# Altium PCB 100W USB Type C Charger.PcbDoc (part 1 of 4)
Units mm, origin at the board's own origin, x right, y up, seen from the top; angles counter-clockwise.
Board outline 79.45 x 55.68 mm, 4 copper layers (Top Layer, Signal Layer 1, Signal Layer 2, Bottom Layer), stack 1.565 mm thick; 161 components, 84 nets, 462 pads, 2175 vias.
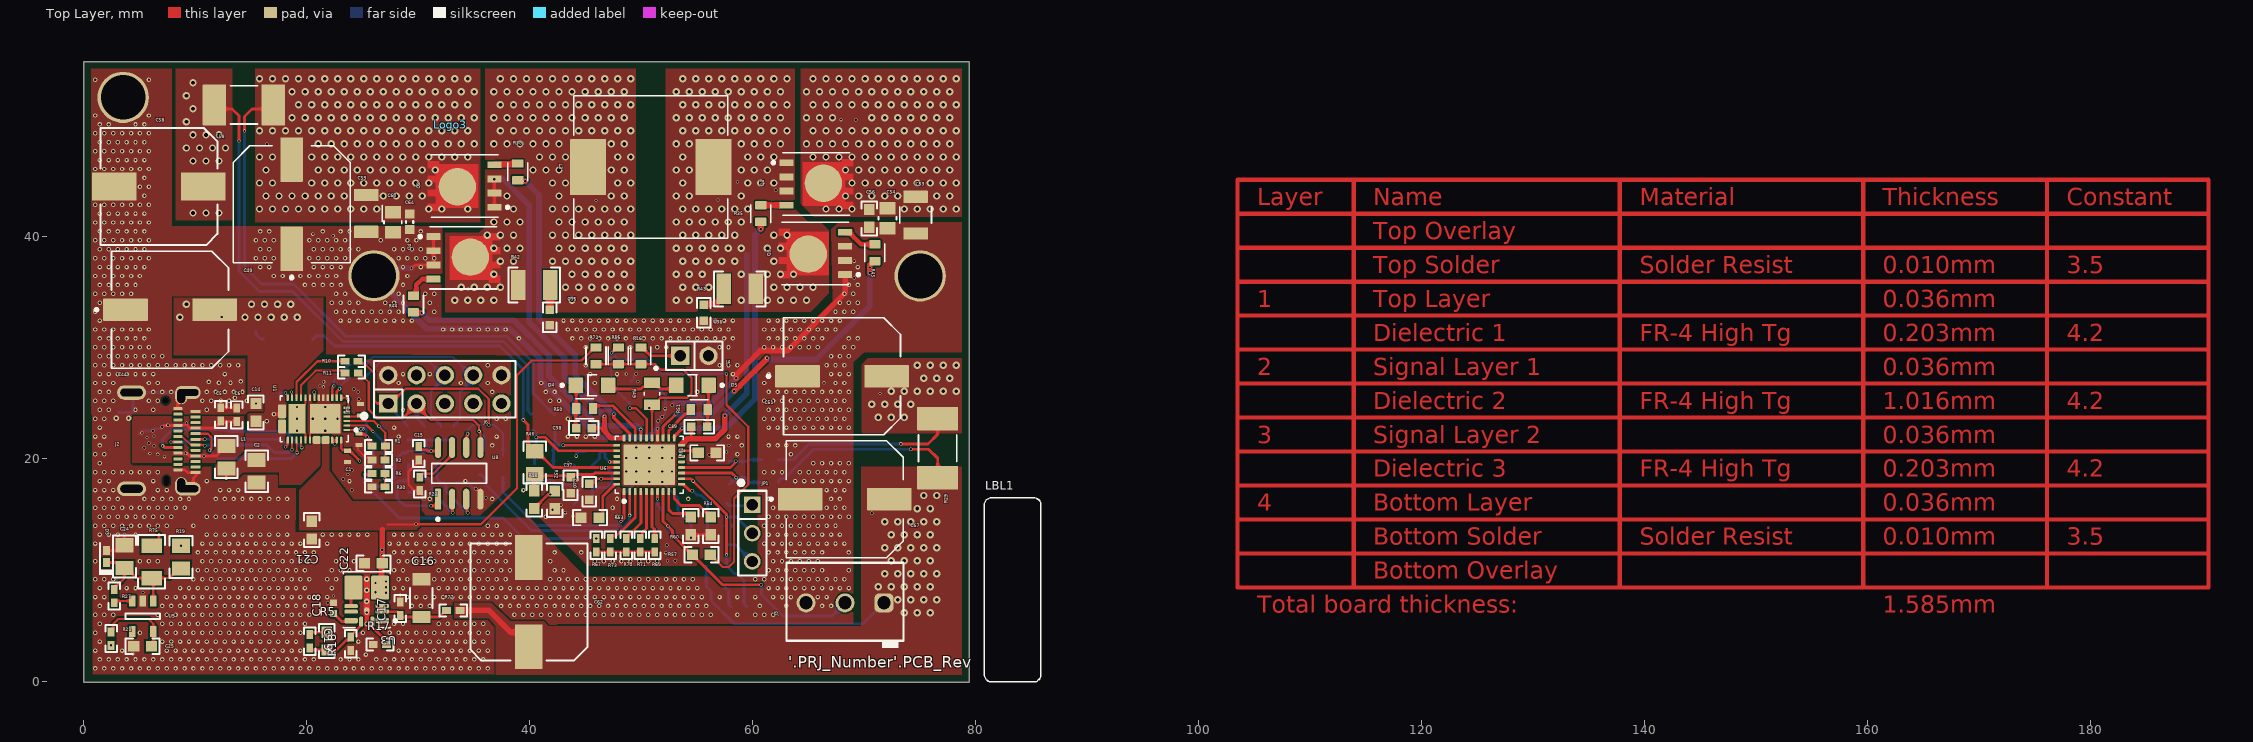
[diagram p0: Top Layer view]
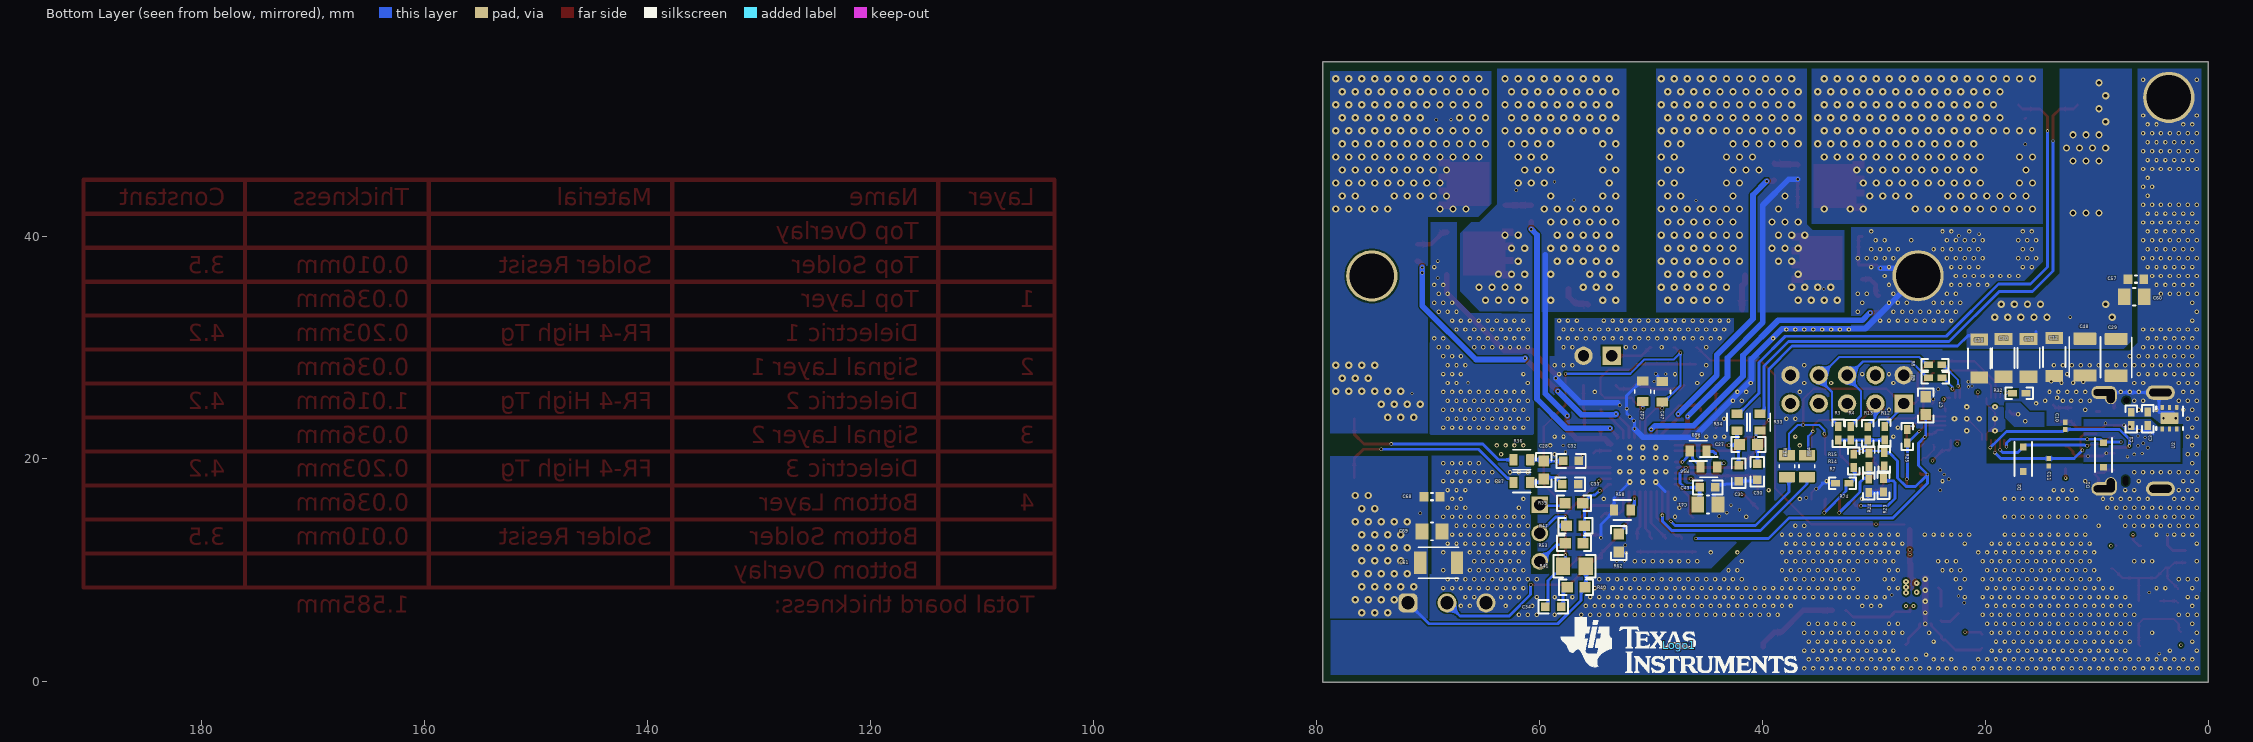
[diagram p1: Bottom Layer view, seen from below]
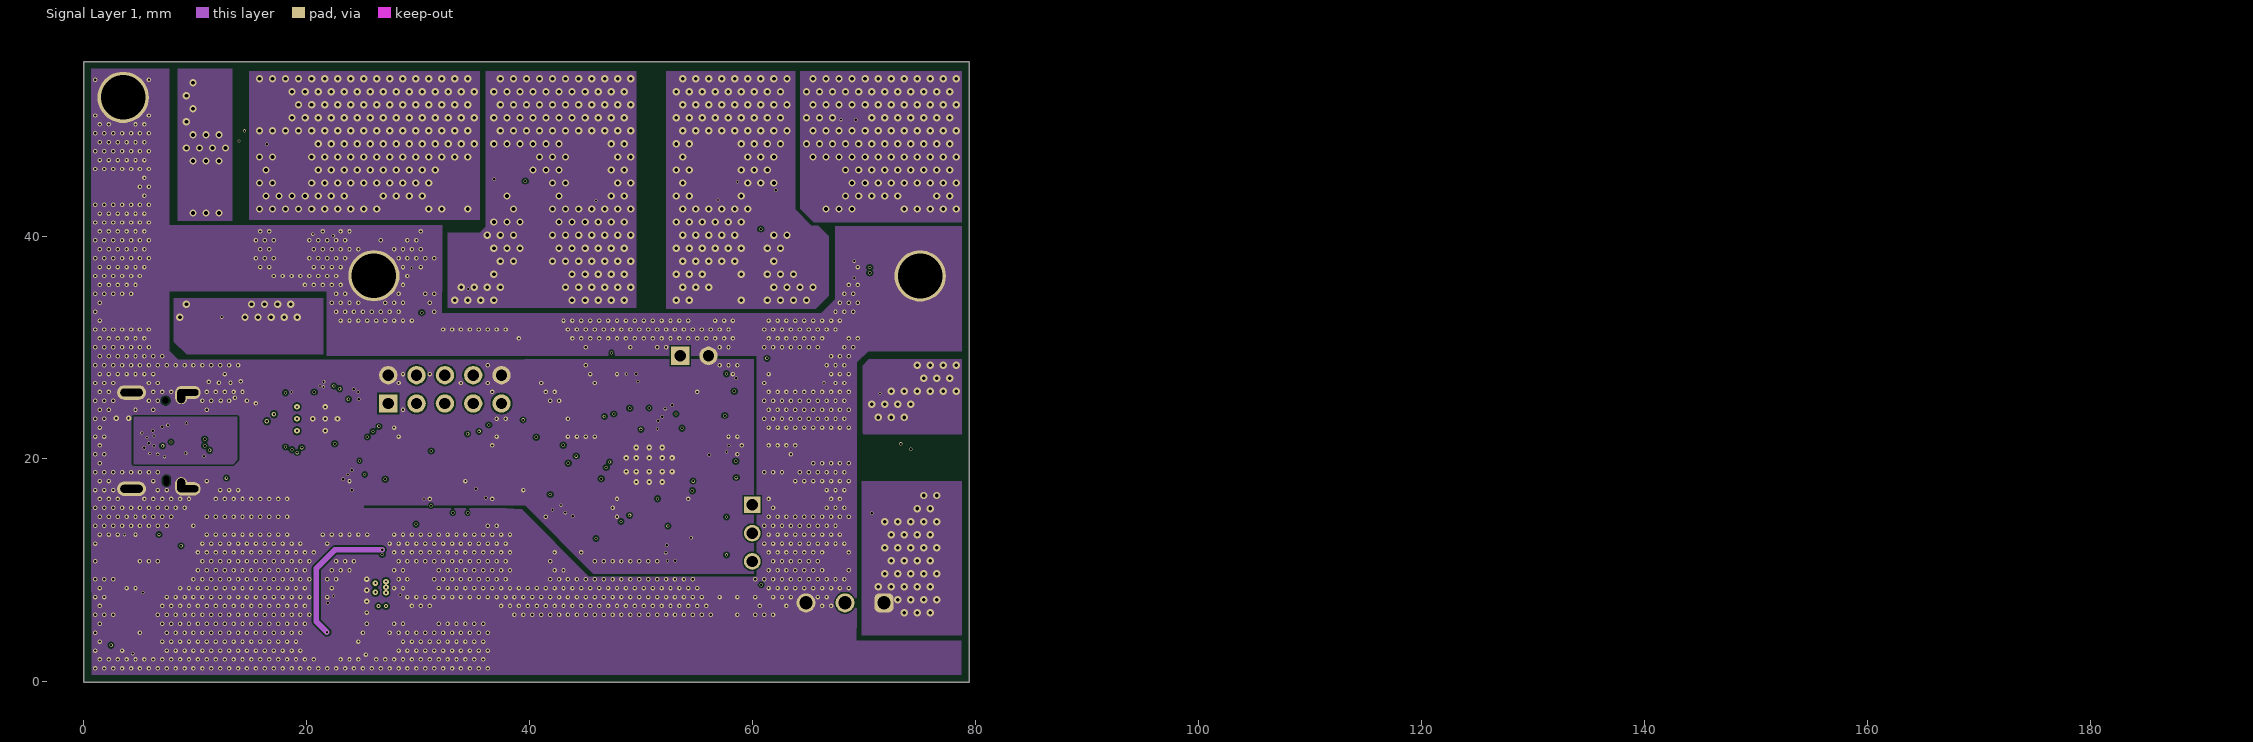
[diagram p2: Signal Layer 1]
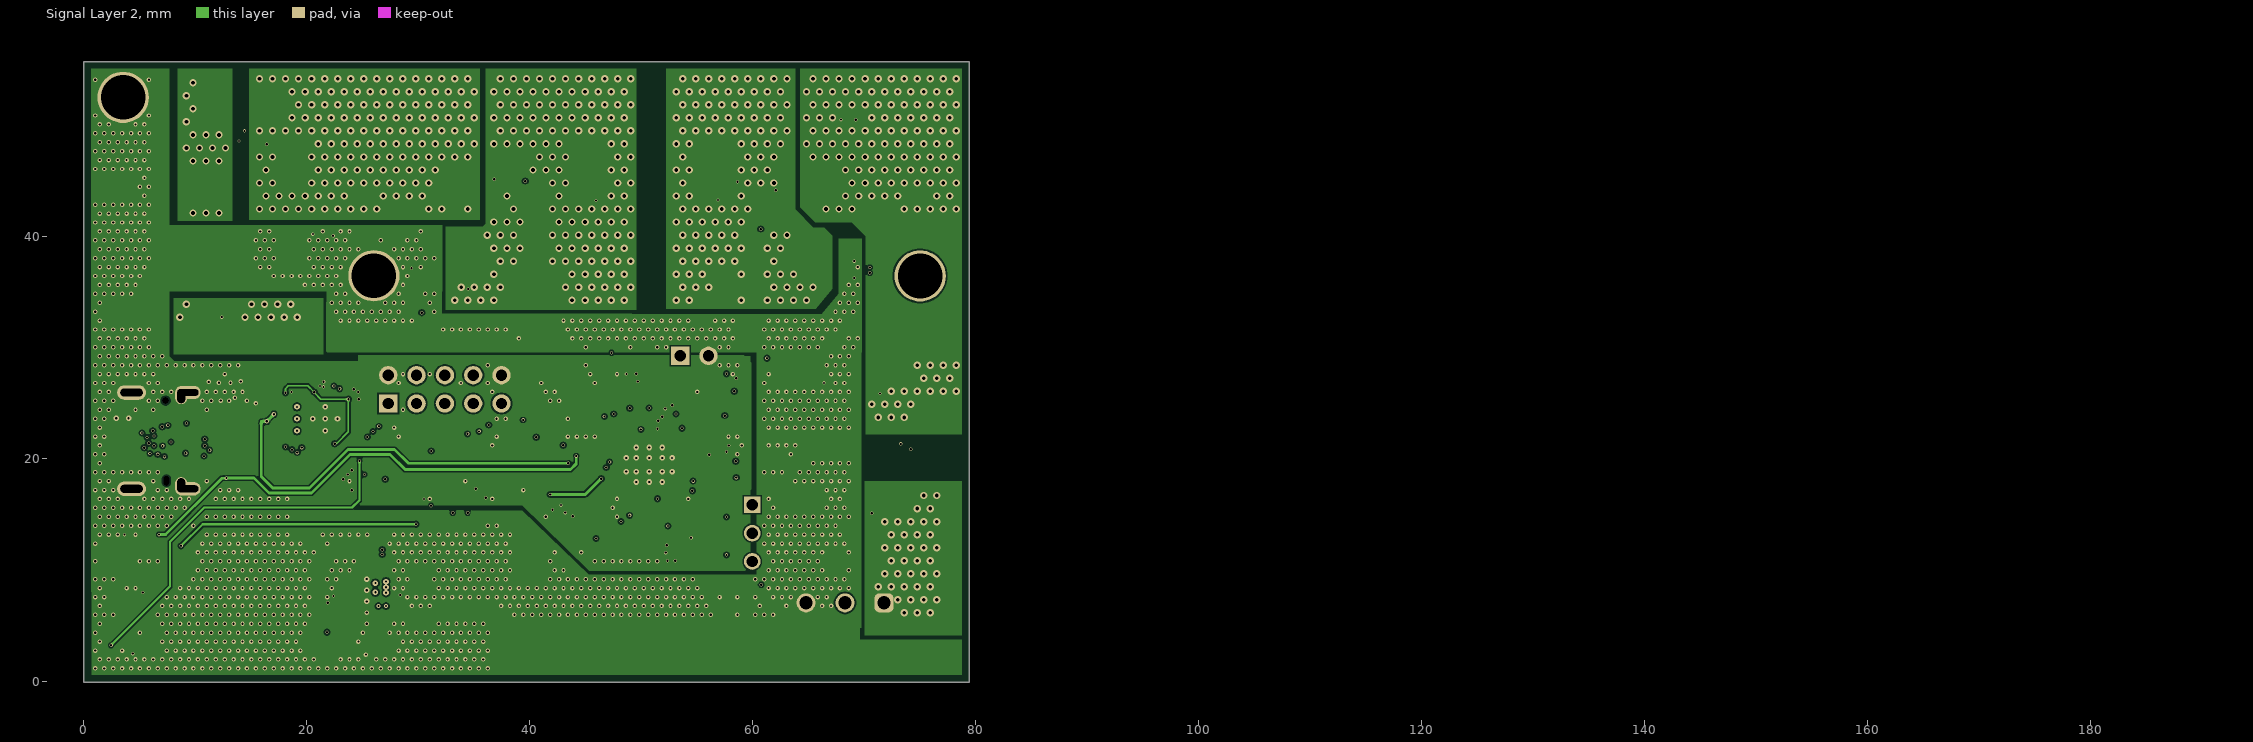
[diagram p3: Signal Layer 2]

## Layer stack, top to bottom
Top Solder: solder mask 0.0102, Solder Resist, Dk 3.5
Top Layer: signal copper 0.0356
Dielectric 1: prepreg 0.2032, FR-4 High Tg, Dk 4.2
Signal Layer 1: signal copper 0.0356
Dielectric 2: core 1.016, FR-4 High Tg, Dk 4.2
Signal Layer 2: signal copper 0.0356
Dielectric 3: prepreg 0.2032, FR-4 High Tg, Dk 4.2
Bottom Layer: signal copper 0.0356
Bottom Solder: solder mask 0.0102, Solder Resist, Dk 3.5

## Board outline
-0.018,-0.02 -0.018,55.656 79.433,55.656 79.433,-0.02

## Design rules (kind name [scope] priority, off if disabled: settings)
AcuteAngle [All] p1: minimum=4.50000000000000E+0001 checktracksonly=FALSE
AssemblyTestPointUsage [All] p1: valid=2
BoardOutlineClearance BoardOutlineClearance_MountingHoles [OnCopper and InComponentClass('Mounting Holes')] p1: gap=1 ignorepadtopadclearanceinfootprint=FALSE
BoardOutlineClearance BoardOutlineClearance_Poly [OnCopper and IsPoly] p2: gap=0.635 ignorepadtopadclearanceinfootprint=FALSE
BoardOutlineClearance [OnCopper and Not InComponentClass('Logo') and not InComponentClass('FiducialMark') and not InRegion(1000,500,4000,800) and not InPoly] p3: gap=1.016 ignorepadtopadclearanceinfootprint=FALSE
Clearance "VBUS V50" [(InComponent('U1') AND InNet('VBUS')) Or InComponent('U1') And InNet('P5V0')] p1: gap=0.15 ignorepadtopadclearanceinfootprint=TRUE
Clearance Clearance_Poly [InPolygon] p2: gap=0.15 ignorepadtopadclearanceinfootprint=TRUE
Clearance [All] p3: gap=0.15 ignorepadtopadclearanceinfootprint=TRUE
ComponentClearance ComponentClearance_MountingHoles_FiducialMarks [InComponentClass('Mounting Holes') vs InComponentClass('FiducialMark')] p1: gap=1.27 collisioncheckmode=3 verticalgap=0.254 showdistances=FALSE
ComponentClearance ComponentClearance_Shunt [InComponentClass('Header') vs InComponentClass('Shunt')] p2: gap=0.15 collisioncheckmode=3 verticalgap=0.15 showdistances=FALSE
ComponentClearance ComponentClearance_Logo [InComponentClass('Logo')] p3: gap=0.254 collisioncheckmode=3 verticalgap=0.254 showdistances=FALSE
ComponentClearance ComponentClearance_ScrewToNut [(HasFootprint('NY PMS 440 0025 PH')) vs (HasFootprint('Keystone_1902C'))] p4: gap=0.127 collisioncheckmode=3 verticalgap=0.254 showdistances=FALSE
ComponentClearance ComponentClearance_MountingHoles [InComponentClass('Mounting Holes')] p5: gap=0.254 collisioncheckmode=3 verticalgap=2540 showdistances=FALSE
ComponentClearance ComponentClearance_SmallPassives [HasFootprint('0201*') or HasFootprint('0402*') or HasFootprint('0508') or HasFootprint('0603*') or HasFootprint('0612') or HasFootprint('0805*') or HasFootprint('0815*') or HasFootprint('0830*') or HasFootprint('1206*') or HasFootprint('1210*') or HasFootprint('1808*') or HasFootprint('1812*') or HasFootprint('1825*') or HasFootprint('2010*') or HasFootprint('2220*') or HasFootprint('2225*') or HasFootprint('2512*') or HasFootprint('2728*') or HasFootprint('3518*') vs HasFootprint('0201*') or HasFootprint('0402*') or HasFootprint('0508') or HasFootprint('0603*') or HasFootprint('0612') or HasFootprint('0805*') or HasFootprint('0815*') or HasFootprint('0830*') or HasFootprint('1206*') or HasFootprint('1210*') or HasFootprint('1808*') or HasFootprint('1812*') or HasFootprint('1825*') or HasFootprint('2010*') or HasFootprint('2220*') or HasFootprint('2225*') or HasFootprint('2512*') or HasFootprint('2728*') or HasFootprint('3518*')] p6: gap=0.254 collisioncheckmode=3 verticalgap=0.254 showdistances=FALSE
ComponentClearance ComponentClearance_THtoSMT [IsThruComponent vs IsSMTComponent] p7: gap=0.254 collisioncheckmode=3 verticalgap=0.254 showdistances=FALSE
ComponentClearance ComponentClearance_THtoTH [IsThruComponent vs IsThruComponent] p8: gap=0.1 collisioncheckmode=3 verticalgap=0.1 showdistances=FALSE
ComponentClearance [All] p9: gap=0.254 collisioncheckmode=3 verticalgap=0.254 showdistances=FALSE
DiffPairsRouting [All] p1: maxlimit=2.54 minlimit=0.254 mostfreqgap=0.254 toplayer_minwidth=0.381 toplayer_maxwidth=0.381 toplayer_prefwidth=0.381 midlayer1_minwidth=0.381 midlayer1_maxwidth=0.381 midlayer1_prefwidth=0.381 midlayer2_minwidth=0.381 midlayer2_maxwidth=0.381 midlayer2_prefwidth=0.381 bottomlayer_minwidth=0.381 bottomlayer_maxwidth=0.381 bottomlayer_prefwidth=0.381 maxuncoupledlength=25.4
FabricationTestPointUsage TestPointUsage [All] p1: valid=2 allowmultiple=FALSE
FabricationTestpoint Testpoint [All] p1: side=3 testpointundercomponent=TRUE minsize=1.016 maxsize=2.54 preferedsize=1.524 minholesize=0 maxholesize=1.016 preferedholesize=0.813 testpointgrid=0.025 allowsidetop=TRUE allowsidebottom=TRUE usegrid=TRUE gridtolerance=0
FanoutControl Fanout_LCC [IsLCC] p1: bgadir=Out bgaviamode=Centered fanoutstyle=Auto fanoutdirection=Alternating viagrid=0.025 // Fanout_LCC (Default Rule)
FanoutControl Fanout_BGA [IsBGA] p2: bgadir=Out bgaviamode=Centered fanoutstyle=Auto fanoutdirection=Alternating viagrid=0.025 // Fanout_BGA (Default Rule)
FanoutControl Fanout_Default [All] p4: bgadir=Out bgaviamode=Centered fanoutstyle=Auto fanoutdirection=Alternating viagrid=0.025 // Fanout_Default (Default Rule)
FanoutControl Fanout_Small [(CompPinCount < 5)] p5: bgadir=Out bgaviamode=Centered fanoutstyle=Auto fanoutdirection=OutThenIn viagrid=0.025 // Fanout_Small (Default Rule)
HoleSize [All] p1: absolutevalues=TRUE maxlimit=6.375 minlimit=0.2 maxpercent=80.000 minpercent=20.000
MinimumAnnularRing MinimumAnnularRing_ThermalPadVias [IsVia and InAnyComponent] p1: minimumring=0.15
MinimumAnnularRing [All] p2: minimumring=0.2
MinimumSolderMaskSliver MinimumSolderMaskSliver_Logo [InComponentClass('Logo') vs InComponentClass('Logo')] p1: minsoldermaskwidth=0.018
MinimumSolderMaskSliver [All] p2: minsoldermaskwidth=0.1
PlaneConnect [All] p1: planeconnectstyle=Relief reliefexpansion=0.254 reliefentries=4 reliefconductorwidth=0.254 reliefairgap=0.254
PolygonConnect [All] p1: connectstyle=Direct reliefconductorwidth=0.254 reliefentries=4 polygonreliefangle="90 Angle" airgapwidth=0.254
RoutingVias ThermalPadVias [IsVia and InAnyComponent] p1: holewidth=0.2 width=0.5 viastyle="Through Hole" minholewidth=0.2 minwidth=0.5 maxholewidth=0.33 maxwidth=0.6
RoutingVias [All] p2: holewidth=0.406 width=0.864 viastyle="Through Hole" minholewidth=0.2 minwidth=0.61 maxholewidth=1.016 maxwidth=1.651
SilkToBoardRegionClearance [Not ((IsComment or IsDesignator) And (Hide <> 'False')) and not InRegion(1000,500,4000,800)] p1:
SilkToSilkClearance SilkToSilkClearance_Pb-FreeLogo [(HasFootprint('Pb-Free_Overlay_Medium') OR HasFootprint('Pb-Free_Overlay_Small')) vs (HasFootprint('Pb-Free_Overlay_Medium') OR HasFootprint('Pb-Free_Overlay_Small'))] p1: silktosilkclearance=0
SilkToSilkClearance [All] p2: silktosilkclearance=0.1
SilkToSolderMaskClearance SilkToComponentPadClearance [(IsPad or IsFill or IsRegion) and InAnycomponent] p1: minsilkscreentomaskgap=0.127 clearancetoexposedcopper=TRUE
SilkToSolderMaskClearance "Silk to Solder Mask Opening" [All] p2: minsilkscreentomaskgap=0.1 clearancetoexposedcopper=FALSE
SolderMaskExpansion [All] p1: expansion=0.05 istentingtop=FALSE
UnRoutedNet [All] p1: checkbadconnections=TRUE
Width [All] p1: maxlimit=2.54 minlimit=0.152 preferedwidth=0.254
14 further rules are at their usual default settings.

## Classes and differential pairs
net class HHV: BAT HIDRV2 NetC36_1 NetC39_1 NetQ1_4 P_OUT SRN SRP SW2
net class LV: LDO_3V3 LODRV1 LODRV2 PGND
net class HV: ACN ACP ACUV HIDRV1 NetC35_1 NetC38_2 NetQ2_4 PPHV SW1 VSYS
component class "PD Controller": C1 C2 C3 C4 C5 C6 C7 C8 C9 C10 C11 C12 C13 C14 C15 C16 C17 C18 C19 C20 C21 C22 C24 C25 C70 D1 D2 D3 J2 J6 L1 R1 R2 R3 R4 R5 R6 R7 R8 R9 R10 R11 R12 R13 R14 R15 R17 R18 R19 R21 R22 R23 R24 R25 R27 R30 R32 R74 R75 R77 U1 U2 U3 U5 U8
component class Header: J4 J6 JP1
component class "Charger BQ25756": C27 C28 C29 C30 C31 C32 C33 C34 C35 C36 C37 C38 C39 C40 C41 C42 C43 C44 C47 C48 C49 C51 C53 C54 C56 C57 C58 C59 C60 C61 C62 C63 C64 C67 C68 C69 D4 D5 J3 J4 JP1 L3 Q1 Q2 Q3 Q4 R16 R29 R31 R33 R34 R35 R36 R37 R38 R39 R40 R41 R42 R43 R44 R45 R46 R47 R48 R49 R50 R51 R52 R53 R54 R55 R56 R57 R58 R59 R60 R61 R62 R63 R64 R67 R68 R69 R70 R71 R72 R73 U6
component class Logo: Logo1
component class "100W USB Type C Charger_Hardware": LBL1 Logo1 Logo3 ZZ1 ZZ2 ZZ3 ZZ4
component class AssemblyNote: ZZ1 ZZ2 ZZ3 ZZ4
component class Label: LBL1

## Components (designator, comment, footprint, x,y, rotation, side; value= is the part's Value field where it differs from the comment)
C1 "CL05A106MP5NUNC" 0402_070 23.663,20.238 r270 top value=10uF
C2 "GRM21BR61H475KE51L" 0805_HV 15.509,18.896 r270 top value=4.7uF
C3 "C0402C103J5RACTU" 0402 5.435,23.604 r90 bottom value=0.01uF
C4 "C0402C103J5RACTU" 0402 6.908,23.591 r90 bottom value=0.01uF
C5 "C0402C103J5RACTU" 0402 12.285,23.995 r90 top value=0.01uF
C6 "C0402C103J5RACTU" 0402 13.733,23.96 r90 top value=0.01uF
C7 "CMP-0006808-4" 0603 25.34,24.783 r270 bottom value=0.1uF
C8 "CL05A106MP5NUNC" 0402_070 24.698,21.773 r90 top value=10uF
C9 "CL05A106MP5NUNC" 0402_070 24.82,24.418 r270 top value=10uF
C10 "CGA1A2X7R1H331K030BA" 0201_033 12.819,22.968 r90 bottom value=330pF
C11 "CGA1A2X7R1H331K030BA" 0201_033 14.315,19.714 r270 bottom value=330pF
C12 "CL31B106KBHNNNE" 1206_180 13.818,29.154 r270 bottom value=10uF
C13 "CL31B106KBHNNNE" 1206_180 20.552,29.008 r270 bottom value=10uF
C14 "GCM188R71H104KA57D" 0603 15.451,24.183 r90 top value=0.1uF
C15 "GMK105BJ104KV-F" 0402 30.064,20.504 r270 top value=0.1uF
C16 "C3216X7S2A225K160AB" 1206_180 30.289,7.518 r90 top value=2.2uF
C17 "GRM155R62A104KE14D" 0402 28.387,6.576 r90 top value=0.1uF
C18 "0402YD105KAT2A" FP-0402YD105KAT2A_0402-IPC_B 22.404,6.617 r90 top value=1µF
C19 "C0402C100C8GACTU" 0402 20.288,3.651 r270 top value=10pF
C20 "CL31B106KBHNNNE" 1206_180 16.119,29.069 r270 bottom value=10uF
C21 "CL10A226MP8NUNE" 0603 20.456,13.619 r270 top value=22uF
C22 "CL10A226MP8NUNE" 0603 25.982,10.653 r180 top value=22uF
C24 "C2012X7S2A105K125AB" 0805_HV 3.656,11.249 r90 top value=1uF
C25 "CGA3E3X5R1A225K080AB" 0603 5.291,3.216 r180 top value=2.2uF
C27 "C0603C474K4RACTU" 0603 41.252,21.298 r0 bottom value=0.47uF
C28 "C0603C474K4RACTU" 0603 59.615,19.004 r270 bottom value=0.47uF
C29 "GCJ32DC72A475KE01L" FP-GCJ32DC72A475KE01L_1210-MFG 8.263,29.117 r90 bottom value=4.7µF
C30 "HMK107B7104KAHT" 0603_HV 40.452,18.868 r270 bottom value=0.1uF
C31 "HMK107B7104KAHT" 0603_HV 42.14,18.724 r270 bottom value=0.1uF
C32 "HMK107B7104KAHT" 0603_HV 57.169,19.82 r180 bottom value=0.1uF
C33 "HMK107B7104KAHT" 0603_HV 57.227,17.727 r180 bottom value=0.1uF
C34 "GCM1885C2A101JA16D" 0603_HV 58.768,6.744 r0 bottom value=100pF
C35 "06031A330JAT2A" 0603_HV 41.813,32.699 r270 top value=33pF
C36 "06031A330JAT2A" 0603_HV 55.623,33.116 r270 top value=33pF
C37 "HMK107B7104KAHT" 0603_HV 43.671,17.646 r270 top value=0.1uF
C38 "06033C104KAT2A" 0603_HV 44.877,22.776 r180 top value=0.1uF
C39 "06033C104KAT2A" 0603_HV 55.218,22.886 r180 top value=0.1uF
C40 "HMK107B7104KAHT" 0603_HV 45.365,17.07 r270 top value=0.1uF
C41 "08051C105K4Z2A" 0805_150 44.893,15.907 r180 bottom value=1uF
C42 "CGA4J1X7R1E475K125AE" FP-CGA4J1X7R1E475K125AE_0805-MFG 50.731,26.067 r90 bottom value=4.7µF
C43 "HMK107B7104KAHT" 0603_HV 44.922,17.443 r0 bottom value=0.1uF
C44 "PCR1J101MCL1GS" FP-PCR1J101MCL1GS_SMD_RADIAL-MFG 7.745,33.397 r0 top
C47 "CGA4J1X7R1E475K125AE" FP-CGA4J1X7R1E475K125AE_0805-MFG 48.974,26.03 r90 bottom value=4.7µF
C48 "GCJ32DC72A475KE01L" FP-GCJ32DC72A475KE01L_1210-MFG 11.068,29.143 r270 bottom value=4.7µF
C49 "PCR1J101MCL1GS" FP-PCR1J101MCL1GS_SMD_RADIAL-MFG 18.656,42.854 r90 top
C51 "PCR1J101MCL1GS" FP-PCR1J101MCL1GS_SMD_RADIAL-MFG 68.032,27.422 r0 top
C53 "C3225X7R2A106K250AC" FP-C3225X7R2A106K250AC_1210-MFG 74.628,41.879 r90 top value=10µF
C54 "08051C105K4Z2A" 0805_150 72.106,41.593 r270 top value=1uF
C56 "CGA3E2C0G2A101J080AA" 0603 70.454,41.593 r270 top value=100pF
C57 "HMK107B7104KAHT" 0603L 6.485,36.142 r180 bottom value=0.1uF
C58 "EEHZC1J560P" SM_RADIAL_10BMM 6.739,44.444 r180 top value=56uF
C59 "C3225X7R2A106K250AC" FP-C3225X7R2A106K250AC_1210-MFG 25.344,42.024 r90 top value=10µF
C60 "08051C105K4Z2A" 0805_150 6.636,34.555 r180 bottom value=1uF
C61 "GCJ32DC72A475KE01L" FP-GCJ32DC72A475KE01L_1210-MFG 69.047,10.692 r180 bottom value=4.7µF
C62 "EEHZC1J560P" SM_RADIAL_10BMM 39.929,7.163 r90 top value=56uF
C63 "08051C105K4Z2A" 0805_150 27.733,41.235 r270 top value=1uF
C64 "HMK107B7104KAHT" 0603L 29.239,41.271 r270 top value=0.1uF
C67 "PCR1J101MCL1GS" FP-PCR1J101MCL1GS_SMD_RADIAL-MFG 68.267,16.396 r0 top
C68 "HMK107B7104KAHT" 0603L 69.643,16.617 r180 bottom value=0.1uF
C69 "08051C105K4Z2A" 0805_150 69.643,13.505 r180 bottom value=1uF
C70 "CL31B106KBHNNNE" 1206_180 18.382,29.072 r270 bottom value=10uF
D1 "CDSOD323-T05C" SOD-323-Bi 9.399,20.368 r90 bottom value=5V
D2 "CDSOD323-T05C" SOD-323-Bi 16.588,19.981 r90 bottom value=5V
D3 "BZT52C9V1T-7" SOD-523 2.04,11.249 r90 top value=9.1V
D4 "V1FM10-M3/H" FP-V1FM10-M3-H_DO-219AB-MFG 45.588,26.612 r180 top
D5 "V1FM10-M3/H" FP-V1FM10-M3-H_DO-219AB-MFG 54.602,26.612 r0 top
J2 "DX07S024JJ2R1300" JAE_DX07S024JJ2R1300 2.493,21.642 r270 top
J3 "OSTTE030161" On-Shore_OSTTE030161 68.299,7.092 r180 top
J4 "90120-0122" CONN_90120-0122 54.782,29.257 r0 top
J6 "PEC05DAAN" CONN_PEC05DAAN 32.401,26.248 r0 top
JP1 "PEC03SAAN" CONN_PEC03SAAN 59.981,13.348 r270 top
L1 "FBMJ2125HM210NT" 0805_HV 12.799,20.162 r270 top value="21 ohm"
L3 "CMLB135T-100MS" FP-CMLB135T-100MS_SMT2_13MM45_12Mm6-MFG 50.876,46.193 r0 top value=10uH
LBL1 "THT-14-423-10" Label_650x200 83.332,8.26 r90 top
Logo1 "Texas Instruments" TI_Stacked_Overlay_Small 47.474,3.298 r180 bottom
Logo3 "FCC disclaimer" FCC_disclaimer 32.901,49.992 r0 top
Q1 "SIR880BDP-T1-RE3" FP-SIR880BDP-T1-RE3_SO-8-MFG 65.717,44.672 r0 top
Q2 "SIR880BDP-T1-RE3" FP-SIR880BDP-T1-RE3_SO-8-MFG 34.171,44.492 r180 top
Q3 "SIR880BDP-T1-RE3" FP-SIR880BDP-T1-RE3_SO-8-MFG 65.641,38.444 r180 top
Q4 "SIR880BDP-T1-RE3" FP-SIR880BDP-T1-RE3_SO-8-MFG 34.044,38.043 r0 top
R1 "RMCF0402FT100K" 0402 26.459,21.16 r180 top value=100k
R2 "RC0402JR-070RL" 0402 26.444,19.912 r0 top value=0
R3 "CRCW04023K30JNED" 0402 33.197,22.303 r270 bottom value=3.3k
R4 "CRCW04023K30JNED" 0402 32.061,22.298 r270 bottom value=3.3k
R5 "RG1608P-4022-B-T5" 0603 21.819,3.657 r90 top value=40.2k
R6 "RMCF0402FT100K" 0402 26.444,18.692 r0 top value=100k
R7 "CMP-0026825-5" 0402 29.08,19.963 r90 bottom value=10k
R8 "CMP-0027004-2" 0402 24.508,28.44 r0 bottom value=0
R9 "CMP-0027004-2" 0402 24.495,27.296 r0 bottom value=0
R10 "CMP-0027004-2" 0402 24.023,28.778 r0 top value=0
R11 "CMP-0027004-2" 0402 24.029,27.719 r0 top value=0
R12 "CRCW04023K30JNED" 0402 29.036,22.314 r90 bottom value=3.3k
R13 "CRCW04023K30JNED" 0402 30.555,22.291 r90 bottom value=3.3k
R14 "CMP-0026825-5" 0402 30.441,19.922 r90 bottom value=10k
R15 "CMP-0026825-5" 0402 31.813,19.821 r90 bottom value=10k
R16 "CRCW06030000Z0EA" FP-CRCW06031R50FKEAHP_0603-MFG 49.981,29.257 r90 top value=0
R17 "CRCW040219K6FKED" 0402 26.577,3.357 r0 top value=19.6k
R18 "ERJ-2RKF1002X" 0402 23.944,3.42 r90 top value=10.0k
R19 "RC0805JR-073R3L" 0805_HV 8.724,11.2 r90 top value=3.3
R21 "CMP-0027004-2" 0402 2.454,3.881 r90 top value=0
R22 "CMP-0026825-5" 0402 30.153,17.759 r90 top value=10k
R23 "CMP-0026825-5" 0402 29.139,17.647 r90 bottom value=10k
R24 "CMP-0026825-5" 0402 30.453,17.582 r90 bottom value=10k
R25 "CMP-0027004-2" 0402 26.994,22.027 r270 bottom value=0
R27 "CMP-0027004-2" 0402 2.725,7.698 r90 top value=0
R29 "WSL25125L000FEA" FP-WSL25125L000FEA_2512-MFG 76.611,20.971 r270 top value=5m
R30 "RC0402JR-070RL" 0402 26.444,17.504 r0 top value=0
R31 "WSL25125L000FEA" FP-WSL25125L000FEA_2512-MFG 14.374,51.771 r0 top value=5m
R32 "RC0402JR-070RL" 0402 16.959,25.887 r180 bottom value=0
R33 "CRCW060310R0FKEB" FP-CRCW060310R0FKEB_0603-MFG 40.207,23.311 r90 bottom value=10
R34 "CRCW060310R0FKEB" FP-CRCW060310R0FKEB_0603-MFG 42.282,23.298 r90 bottom value=10
R35 "CRCW06030000Z0EA" FP-CRCW06031R50FKEAHP_0603-MFG 60.739,42.017 r270 top value=0
R36 "CRCW060310R0FKEB" FP-CRCW060310R0FKEB_0603-MFG 61.583,19.931 r180 bottom value=10
R37 "CRCW060310R0FKEB" FP-CRCW060310R0FKEB_0603-MFG 61.583,17.899 r180 bottom value=10
R38 "CRCW06030000Z0EA" FP-CRCW06031R50FKEAHP_0603-MFG 38.942,45.762 r270 top value=0
R39 "RT0603BRD0730K1L" 0603 56.923,16.026 r0 bottom value=30.1k
R40 "CRCW06031R10JNEA" 0603 56.706,8.476 r180 bottom value=1.1
R41 "ERJ-PB6B2493V" 0805_HV 56.859,10.381 r180 bottom value=249k
R42 "CRCW12103R30FKEAHP" 1210 40.413,35.597 r180 top value=3.30
R43 "CRCW12103R30FKEAHP" 1210 58.853,35.268 r0 top value=3.30
R44 "CRCW06030000Z0EA" FP-CRCW06031R50FKEAHP_0603-MFG 29.582,33.903 r90 top value=0
R45 "CRCW06030000Z0EA" FP-CRCW06031R50FKEAHP_0603-MFG 70.975,38.502 r90 top value=0
R46 "CRCW08051M00FKEAC" 0805_HV 40.47,19.677 r90 top value=1.00Meg
R47 "RT0603BRD0724K9L" 0603 56.787,13.996 r0 bottom value=24.9k
R48 "RC0603FR-07294KL" 0603 40.423,16.348 r90 top value=294k
R49 "CRCW08050000Z0EA" FP-CRCW080510R0JNEAHP_0805-MFG 50.981,25.85 r270 top value=0
R50 "CRCW06030000Z0EA" FP-CRCW06031R50FKEAHP_0603-MFG 44.933,24.517 r180 top value=0
R51 "CRCW06030000Z0EA" FP-CRCW06031R50FKEAHP_0603-MFG 55.218,24.425 r0 top value=0
R52 "RC0603FR-0764K9L" 0603 42.254,16.332 r90 top value=64.9k
R53 "RT0603BRD0711K4L" 0603 56.891,12.433 r0 bottom value=11.4k
R54 "RC0603FR-072K49L" 0603 56.237,13.996 r90 top value=2.49k
R55 "CRCW06030000Z0EA" FP-CRCW06031R50FKEAHP_0603-MFG 47.963,29.257 r270 top value=0
R56 "CRCW06030000Z0EA" FP-CRCW06031R50FKEAHP_0603-MFG 44.803,19.272 r0 bottom value=0
R57 "RC0603FR-075K23L" 0603 55.411,11.397 r0 top value=5.23k
R58 "CRCW06030000Z0EA" FP-CRCW06031R50FKEAHP_0603-MFG 52.56,15.423 r0 bottom value=0
R59 "CRCW06030000Z0EA" FP-CRCW06031R50FKEAHP_0603-MFG 45.767,20.725 r0 bottom value=0
R60 "M55342E12B10B1T" 0603 54.453,13.996 r90 top value=10.1k
R61 "CRCW06033K01FKEA" 0603 55.936,20.541 r180 top value=3.01k
R62 "RC0603FR-0730K1L" 0603 52.905,12.465 r90 bottom value=30.1k
R63 "RC0603FR-07100KL" 0603 45.417,14.745 r0 top value=100k
R64 "CRCW08050000Z0EA" FP-CRCW080510R0JNEAHP_0805-MFG 36.011,19.353 r90 bottom value=0
R67 "CRCW04021R10FKED" 0402 45.971,12.267 r270 top value=1.10
R68 "CRCW08050000Z0EA" FP-CRCW080510R0JNEAHP_0805-MFG 37.804,19.353 r90 bottom value=0
R69 "RC0402FR-0710K5L" 0402 51.231,12.267 r270 top value=10.5k
R70 "RC0402FR-0710K5L" 0402 48.681,12.267 r270 top value=10.5k
R71 "RC0402FR-0710K5L" 0402 49.931,12.267 r270 top value=10.5k
R72 "CRCW06030000Z0EA" FP-CRCW06031R50FKEAHP_0603-MFG 45.961,29.257 r270 top value=0
R73 "RC0402FR-0710K5L" 0402 47.234,12.267 r270 top value=10.5k
R74 "CMP-0026825-5" 0402 32.824,17.832 r180 bottom value=10k
R75 "RC1206FR-077K5L" 1206 6.091,10.765 r90 top value=7.50k
R77 "CMP-0027004-2" 0402 33.156,6.41 r0 top value=0
U1 "TPS25751DREFR" RJK0038B-MFG 20.694,23.599 r270 top
U2 "TVS2200DRVR" DRV0006A 3.474,23.658 r270 bottom
U3 "TPSM365R3RDNR" RDN0011A-MFG 25.39,7.452 r180 top
U5 "TPS76333DBVR" DBV0005A_N 5.291,5.889 r270 top
U6 "BQ25756RRVT" RRV0036A-MFG 50.731,19.483 r90 top
U8 "CAT24C512WI-GT3" FP-CAT24C512WI-GT3_SOIC8-IPC_C 33.682,18.711 r90 top
ZZ1 "This Assembly Note is for PCB labels only" AssemblyNoteLabel -21.328,65.943 r0 top
ZZ2 "These assemblies are ESD sensitive, ESD precautions shall be observed." AssemblyNote -21.328,63.178 r0 top
ZZ3 "These assemblies must be clean and free from flux and all contaminants. Use of no clean flux is not acceptable." AssemblyNote -21.328,60.928 r0 top
ZZ4 "These assemblies must comply with workmanship standards IPC-A-610 Class 2, unless otherwise specified." AssemblyNote -21.328,58.679 r0 top

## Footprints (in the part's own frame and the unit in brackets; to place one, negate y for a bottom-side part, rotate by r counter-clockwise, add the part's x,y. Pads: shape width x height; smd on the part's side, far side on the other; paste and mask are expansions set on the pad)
0201_033 [mm] "SMD, 2-Leads, Height 0.33mm"
  rect 0.46x0.42 smd mask+0.048: 1(-0.33,0) 2(0.33,0)
  body extent -0.31,-0.16 0.31,0.16, height 0.33
0402 [mm] "0402 from SM-752 data"
  rect 0.8x0.6 smd: 1(-0.6,0) 2(0.6,0)
  silkscreen extent -1.22,-0.52 1.22,0.52, body extent -0.55,-0.3 0.55,0.3, height 0.6
0402_070 [mil] "SMD, 2-Leads, Body 1.2x0.7mm, Height 0.7mm"
  rect 15x24 smd: 1(-20,0) 2(20,0)
  body extent -24,-14 24,14, height 28
0603 [mm] "0603 from SM-752 data"
  rect 1x0.95 smd: 1(-0.8,0) 2(0.8,0)
  silkscreen extent -1.52,-0.69 1.52,0.69, body extent -0.87,-0.47 0.87,0.47, height 1
0603_HV [mil] "Ernesto recommended land pattern.  26 mil between pads."
  rect 30x30 smd: 1(-28,0) 2(28,0)
  silkscreen extent -52,-24 52,24, body extent -34,-19 34,19, height 39
0603L [mm] "0603 from SM-752 data"
  rect 0.8x0.85 smd: 1(-0.7,0) 2(0.7,0)
  silkscreen extent -0.07,-0.33 0.07,0.33, body extent -0.87,-0.47 0.87,0.47, height 1
0805_150 [mm] "0805 / 1.5 mm height"
  rect 1.15x1.45 smd: 1(-0.9,0) 2(0.9,0)
  silkscreen extent -0.1,-0.8 0.1,0.8, body extent -1.1,-0.72 1.1,0.72, height 1.5
0805_HV [mil] "0805 with 30mil clearance between pads"
  rect 50x63 smd: 1(-40,0) 2(40,0)
  silkscreen extent -74,-40 74,40, body extent -43,-29 43,29, height 57
1206 [mm] "1206 from SM-752 data"
  rect 1.3x1.85 smd: 1(-1.45,0) 2(1.45,0)
  silkscreen extent -2.4,-1.21 2.4,1.21, body extent -1.7,-0.9 1.7,0.9, height 1.35
1206_180 [mm] "1206_180"
  rect 1.1x1.6 smd: 1(-1.7,0) 2(1.7,0)
  silkscreen extent -0.9,-1 0.9,1, body extent -1.75,-0.95 1.75,0.95, height 1.8
1210 [mm] "1210 from SM-752 data"
  rect 1.3x2.7 smd: 1(-1.45,0) 2(1.45,0)
  silkscreen extent -2.32,-1.57 2.32,1.57, body extent -1.7,-1.35 1.7,1.35, height 1.35
AssemblyNote [mm] "Assembly Note"
AssemblyNoteLabel [mm] "Assembly Note for PCB Labels"
CONN_90120-0122 [mm] "Molex"
  rect 1.65x1.65 hole 1.016 mask+0: 1(-1.27,0)
  round 1.65 hole 1.016 mask+0: 2(1.27,0)
  silkscreen extent -3.56,-1.27 2.54,1.27, body extent -2.54,-1.27 2.54,1.27, height 9.29
CONN_PEC03SAAN [mm] "SULLINS"
  rect 1.5x1.5 hole 1.016: 1(-2.54,0)
  round 1.5 hole 1.016: 2(0,0) 3(2.54,0)
  silkscreen extent -4.72,-1.27 3.81,1.27, body extent -3.84,-1.3 3.84,1.3, height 8.38
CONN_PEC05DAAN [mm] "SULLINS"
  rect 1.65x1.65 hole 1.016 mask+0: 1(-5.08,-1.27)
  round 1.65 hole 1.016 mask+0: 2(-5.08,1.27) 3(-2.54,-1.27) 4(-2.54,1.27) 5(0,-1.27) 6(0,1.27) 7(2.54,-1.27) 8(2.54,1.27) 9(5.08,-1.27) 10(5.08,1.27)
  silkscreen extent -7.45,-2.6 6.35,2.54, body extent -6.35,-2.54 6.35,2.54, height 8.38
DBV0005A_N [mm] "SOT23, 5-Leads, Body 2.9x1.6mm, Pitch 0.95mm, Lead Span 2.8mm, IPC Medium Density"
  rrect17% 1x0.6 smd: 1(-1.375,0.95) 2(-1.375,0) 3(-1.375,-0.95) 4(1.375,-0.95) 5(1.375,0.95)
  silkscreen extent -0.25,-1.55 0.25,1.55, body extent -1.42,-1.46 1.42,1.46, height 1.09
DRV0006A [mm] "SON, 6-Leads, Body 2x2mm, Pitch 0.65mm, Thermal Pad 1.6x1mm, TI Recommended"
  rrect33% 0.45x0.3 smd: 1(-0.975,0.65) 2(-0.975,0) 3(-0.975,-0.65) 4(0.975,-0.65) 5(0.975,0) 6(0.975,0.65)
  rrect14% 1x0.7 on Bottom Paste: 7(0,-0.45) 7(0,0.45)
  rrect10% 1x1.6 smd paste-0.5: 7(0,0)
  silkscreen extent -1.05,-1.2 1.05,1.2, body extent -1.05,-1.05 1.05,1.05, height 0.81
FCC_disclaimer [mm]
FP-0402YD105KAT2A_0402-IPC_B [mm]
  rrect16% 0.608x0.658 smd paste+0 mask+0: 1(-0.475,0) 2(0.475,0)
  body extent -0.93,-0.48 0.93,0.48, height 0.25
FP-C3225X7R2A106K250AC_1210-MFG [mm]
  rrect9% 1.1x2.2 smd paste+0 mask+0: 1(-1.65,0) 2(1.65,0)
  silkscreen extent -0.72,-1.43 0.72,1.43, body extent -2.3,-1.53 2.3,1.53, height 0.25
FP-CAT24C512WI-GT3_SOIC8-IPC_C [mm]
  rrect18% 1.874x0.545 smd paste+0 mask+0: 1(-2.316,1.905)
  rrect100% 1.874x0.545 smd paste+0 mask+0: 2(-2.316,0.635) 3(-2.316,-0.635) 4(-2.316,-1.905) 5(2.316,-1.905) 6(2.316,-0.635) 7(2.316,0.635) 8(2.316,1.905)
  silkscreen extent -4.25,-2.45 0.88,2.45, body extent -3,-2.45 3,2.45, height 1.75
FP-CGA4J1X7R1E475K125AE_0805-MFG [mm]
  rrect13% 0.8x1.05 smd paste+0 mask+0: 1(-0.925,0) 2(0.925,0)
  silkscreen extent -0.15,-0.72 0.15,0.72, body extent -1,-0.63 1,0.63, height 1.45
FP-CMLB135T-100MS_SMT2_13MM45_12Mm6-MFG [mm]
  rrect3% 3.25x5 smd paste+0 mask+0: 1(-5.625,0) 2(5.625,0)
  silkscreen extent -6.9,-6.4 6.9,6.4, body extent -7.35,-6.5 7.35,6.5, height 0.25
FP-CRCW06031R50FKEAHP_0603-MFG [mm]
  rrect13% 0.75x1 smd paste+0 mask+0: 1(-0.75,0) 2(0.75,0)
  silkscreen extent -0.8,-0.9 0.8,0.9, body extent -1.22,-0.6 1.22,0.6, height 0.25
FP-CRCW060310R0FKEB_0603-MFG [mm]
  rrect13% 0.75x1 smd paste+0 mask+0: 1(-0.75,0) 2(0.75,0)
  silkscreen extent -0.8,-0.9 0.8,0.9, body extent -0.77,-0.43 0.77,0.43, height 0.5
FP-CRCW080510R0JNEAHP_0805-MFG [mm]
  rrect11% 0.95x1.45 smd paste+0 mask+0: 1(-0.975,0) 2(0.975,0)
  silkscreen extent -0.13,-0.7 0.13,0.7, body extent -1.55,-0.82 1.55,0.82, height 0.25
FP-GCJ32DC72A475KE01L_1210-MFG [mm]
  rrect9% 1.1x2.05 smd paste+0 mask+0: 1(-1.65,0) 2(1.65,0)
  silkscreen extent -1.8,-1.4 1.8,1.4, body extent -1.6,-1.25 1.6,1.25, height 2.3
FP-PCR1J101MCL1GS_SMD_RADIAL-MFG [mm]
  rrect5% 4x2 smd paste+0 mask+0: 1(-4,0) 2(4,0)
  silkscreen extent -6.72,-5.25 5.25,5.25, body extent -6.25,-5.5 6.25,5.5, height 0.25
FP-SIR880BDP-T1-RE3_SO-8-MFG [mil]
  rrect16% 50x24 smd paste+0 mask+0: 1(-105,75) 2(-105,25) 3(-105,-25) 4(-105,-75)
  round 132.13 smd paste+0 mask+0: 5-6-7-8(25.41,2.72)
  Top Layer region: -48,77 90,77 90,87 130,87 130,63 102,63 102,37 130,37 130,13 102,13 102,-13 130,-13 130,-37 102,-37 102,-63 130,-63 130,-87 90,-87 90,-77 -48,-77
  silkscreen extent -157,-110 118,110, body extent -134,-107 134,107, height 10
FP-V1FM10-M3-H_DO-219AB-MFG [mm]
  rrect8% 1.3x1.4 smd paste+0 mask+0: 1(1.45,0) 2(-1.45,0)
  silkscreen extent -0.43,-0.95 2.79,0.95, body extent -2.2,-1.05 2.2,1.05, height 0.25
FP-WSL25125L000FEA_2512-MFG [mm]
  rrect5% 2.11x3.68 smd paste+0 mask+0: 1(-2.645,0) 2(2.645,0)
  silkscreen extent -1.21,-1.72 1.21,1.72, body extent -3.18,-1.59 3.18,1.59, height 0.89
JAE_DX07S024JJ2R1300 [mm] "Receptacle, USB 3.1 Type C, R/A, SMT"
  rrect37% 0.27x0.9 smd: A1(-2.625,7.55) A2(-2.125,7.55) A3(-1.625,7.55) A4(-1.125,7.55) A5(-0.625,7.55) A6(-0.125,7.55) A7(0.375,7.55) A8(0.875,7.55) A9(1.375,7.55) A10(1.875,7.55) A11(2.375,7.55) A12(2.875,7.55)
  round 0.3 hole 0.6 unplated mask+0.102: ALIGN1(-3.6,4.85)
  rrect100% 0.55x0.3 hole 0.5 slot 0.85 at 0 deg unplated mask+0.102: ALIGN2(3.6,4.915)
  rrect37% 0.27x0.8 smd: B1(2.625,5.95) B2(2.125,5.95) B3(1.625,5.95) B4(1.125,5.95) B5(0.625,5.95) B6(0.125,5.95) B7(-0.375,5.95) B8(-0.875,5.95) B9(-1.375,5.95) B10(-1.875,5.95) B11(-2.375,5.95) B12(-2.875,5.95)
  rrect100% 1.2x2.3 hole 0.6 slot 1.9 at 90 deg: S1(-4.32,6.85) S2(4.32,6.85)
  rrect100% 1.45x1.1 hole 0.7 slot 1.25 at 0 deg: S1(-3.995,6.25) S2(3.995,6.25)
  rrect100% 1.3x2.6 hole 0.7 slot 2 at 90 deg: S3(-4.32,1.8) S4(4.32,1.8)
  body extent -4.47,-0.5 4.47,7.67, height 3.14
Label_650x200 [mil] "Thermal Transfer Label"
  round 1 on Mech13: 0(0,0)
  silkscreen extent -325,-100 325,100, body extent -325,-100 325,100, height 1
On-Shore_OSTTE030161 [mm] "Terminal Block, 3.5mm, 3x1, TH"
  rrect50% 1.7x1.7 hole 1.2: 1(-3.5,0)
  round 1.7 hole 1.2: 2(0,0) 3(3.5,0)
  silkscreen extent -5.25,-3.6 5.25,4.05, body extent -5.75,-3.6 5.75,3.4, height 8.4
RDN0011A-MFG [mm]
  rrect42% 1.2x0.475 smd paste-1000 mask-1000: 1(-1.4,1.962) 8(1.4,1.962)
  rrect57% 1.2x0.35 smd paste-1000 mask-1000: 2(-1.4,1.15) 3(-1.4,0.65) 6(1.4,0.65) 7(1.4,1.15)
  rrect13% 1.6x2.15 smd paste-1000 mask-1000: 4(-1.2,-1) 5(1.2,-1)
  rrect57% 0.35x0.9 smd paste-1000 mask-1000: 9(0.5,2.05) 11(-0.5,2.05)
  round 0.504 smd paste-1000 mask-1000: 10(0,1.005)
  Top Layer region: -0.2,2.4 -0.187,2.45 -0.15,2.487 -0.1,2.5 -0.1,2.5 0.1,2.5 0.15,2.487 0.187,2.45 0.2,2.4 0.2,2.4 0.2,1.515 0.203,1.5 0.212,1.487 0.225,1.478 0.24,1.475 0.24,1.475 0.24,1.475 0.26,1.47 0.275,1.455 0.28,1.435 0.28,1.435 0.28,-1.975 0.267,-2.025 0.23,-2.062 0.18,-2.075 0.18,-2.075 -0.18,-2.075 -0.23,-2.062 -0.267,-2.025 -0.28,-1.975 -0.28,-1.975 -0.28,1.435 -0.275,1.455 -0.26,1.47 -0.24,1.475 -0.24,1.475 -0.24,1.475 -0.225,1.478 -0.212,1.487 -0.203,1.5 -0.2,1.515 -0.2,1.515
  silkscreen extent -2.68,-2.42 2.1,2.6, body extent -2.1,-2.4 2.1,2.6, height 0.25
RJK0038B-MFG [mm]
  rrect50% 0.2x0.6 smd paste+0 mask-1000: 1(1,2.9) 2(0.6,2.9) 3(0.2,2.9) 4(-0.2,2.9) 5(-0.6,2.9) 6(-1,2.9)
  rrect50% 0.6x0.2 smd paste+0 mask-1000: 7(-1.9,2.4) 8(-1.9,2) 9(-1.9,1.6) 10(-1.9,1.2) 11(-1.9,0.8) 12(-1.9,0.4) 13(-1.9,0) 14(-1.9,-0.4) 15(-1.9,-0.8) 16(-1.9,-1.2) 17(-1.9,-1.6) 18(-1.9,-2) 19(-1.9,-2.4) 26(1.9,-2.4) 27(1.9,-2) 28(1.9,-1.6) 29(1.9,-1.2) 30(1.9,-0.8) 31(1.9,-0.4) 36(1.9,1.6) 37(1.9,2) 38(1.9,2.4)
  rrect29% 1.253x0.7 smd paste-1000 mask-1000: 20(-0.677,-2.9) 25(0.677,-2.9)
  rrect40% 0.2x0.6 smd paste-1000 mask-1000: 21(-0.6,-2.9) 22(-0.2,-2.9) 23(0.2,-2.9) 24(0.6,-2.9)
  rrect29% 0.7x0.7 smd paste-1000 mask-1000: 32(1.9,0.2) 34(1.9,1)
  rrect40% 0.6x0.2 smd paste-1000 mask-1000: 33(1.9,0.4) 35(1.9,1.2)
  rrect4% 2.65x2.72 smd paste-1000 mask-1000: 39(0,0.965)
  rrect7% 2.65x1.53 smd paste-1000 mask-1000: 40(0,-1.56)
  silkscreen extent -2.05,-3.05 2.05,3.88, body extent -2.3,-3.35 2.35,3.3, height 0.25
RRV0036A-MFG [mm]
  rrect40% 0.6x0.25 smd paste+0 mask+0: 1(-2.4,2.25) 2(-2.4,1.75) 3(-2.4,1.25) 4(-2.4,0.75) 5(-2.4,0.25) 6(-2.4,-0.25) 7(-2.4,-0.75) 8(-2.4,-1.25) 9(-2.4,-1.75) 10(-2.4,-2.25) 19(2.4,-2.25) 20(2.4,-1.75) 21(2.4,-1.25) 22(2.4,-0.75) 23(2.4,-0.25) 24(2.4,0.25) 25(2.4,0.75) 26(2.4,1.25) 27(2.4,1.75) 28(2.4,2.25)
  rrect40% 0.25x0.6 smd paste+0 mask+0: 11(-1.75,-2.9) 12(-1.25,-2.9) 13(-0.75,-2.9) 14(-0.25,-2.9) 15(0.25,-2.9) 16(0.75,-2.9) 17(1.25,-2.9) 18(1.75,-2.9) 29(1.75,2.9) 30(1.25,2.9) 31(0.75,2.9) 32(0.25,2.9) 33(-0.25,2.9) 34(-0.75,2.9) 35(-1.25,2.9) 36(-1.75,2.9)
  rrect3% 3.6x4.6 smd paste-1000 mask+0: 37(0,0)
  silkscreen extent -3.4,-3.05 2.55,3.05, body extent -2.8,-3.3 2.8,3.3, height 0.25
SM_RADIAL_10BMM [mm] "Nichicon 10x10"
  rect 4x2.5 smd: 1(-4,0) 2(4,0)
  silkscreen extent -5.25,-5.25 5.25,5.25, body extent -5.25,-5.25 5.25,5.25, height 10.5
SOD-323-Bi [mm] "SOD323, 2-Leads, Body 1.9x1.45mm, No Polarity Mark"
  rect 0.6x0.6 smd paste-0.05: 1(-1.1,0) 2(1.1,0)
  silkscreen extent -1.53,-0.77 1.53,0.77, body extent -1.27,-0.65 1.27,0.65, height 1.02
SOD-523 [mm] "NXP Semiconductor recommended land pattern, nominal STEP model"
  rect 0.8x0.6 smd paste-0.05: 1(-0.55,0) 2(0.55,0)
  silkscreen extent -1.65,-0.66 1.2,0.66, body extent -0.8,-0.4 0.8,0.4, height 0.72
TI_Stacked_Overlay_Small [mm]
  silkscreen extent -10.63,-2.49 10.63,2.49

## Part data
C1 C8 C9: library part CMP-0006339-4, "CAP, CERM, 10 uF, 10 V, +/- 20%, X5R, 0402", Cap_Case=0402, Manufacturer="Samsung Electro-Mechanics", TempCo=X5R, Tolerance_%=20%, Value1=Unknown, Value2=10V, ValueDisplayed=10uF
C2: library part CMP-0008309-2, "CAP, CERM, 4.7 uF, 50 V, +/- 10%, X5R, 0805", Cap_Case=0805, Manufacturer=MuRata, Supplier Part Number 1=GRM21BR61H475KE51L-ND, TempCo=X5R, Tolerance_%=10%, Value1=Unknown, Value2=50V, ValueDisplayed=4.7uF
C3 C4 C5 C6: library part CMP-0006236-2, "CAP, CERM, 0.01 uF, 50 V, +/- 5%, X7R, 0402", Cap_Case=0402, Manufacturer=Kemet, Supplier Part Number 1=399-7758-1-ND, TempCo=X7R, Tolerance_%=5%, Value1=Unknown, Value2=50V, ValueDisplayed=0.01uF
C7: "CAP, CERM, 0.1 uF, 16 V, +/- 5%, X7R, 0603", Cap_Case=0603, Manufacturer=AVX, PartNumber=0603YC104JAT2A, Supplier Part Number 1=478-3726-1-ND, TempCo=X7R, Tolerance_%=5%, Value1="0.039 ohm", Value2=16V, ValueDisplayed=0.1uF
C10 C11: library part CMP-0009653-3, "CAP, CERM, 330 pF, 50 V, +/- 10%, X7R, AEC-Q200 Grade 1, 0201", Cap_Case=0201_033, Manufacturer=TDK, Supplier Part Number 1=445-12111-1-ND, TempCo=X7R, Tolerance_%=10%, Value1="8.05302 ohm", Value2=50V, ValueDisplayed=330pF
C12 C13 C20 C70: library part CMP-0008802-2, "CAP, CERM, 10 uF, 50 V, +/- 10%, X7R, 1206", Cap_Case=1206, Manufacturer=Samsung, Supplier Part Number 1=1276-6767-1-ND, TempCo=X7R, Tolerance_%=10%, Value1=Unknown, Value2=50V, ValueDisplayed=10uF
C14: library part CMP-0007144-4, "CAP, CERM, 0.1 uF, 50 V, +/- 10%, X7R, 0603", Cap_Case=0603, Manufacturer=MuRata, Supplier Part Number 1=490-4779-1-ND, TempCo=X7R, Tolerance_%=10%, Value1="0.02 ohm", Value2=50V, ValueDisplayed=0.1uF
C15: library part CMP-0006370-2, "CAP, CERM, 0.1 uF, 35 V, +/- 10%, X5R, 0402", Cap_Case=0402, Manufacturer="Taiyo Yuden", Supplier Part Number 1=587-1994-1-ND, TempCo=X5R, Tolerance_%=10%, Value1=Unknown, Value2=35V, ValueDisplayed=0.1uF
C16: library part CMP-0008724-2, "CAP, CERM, 2.2 uF, 100 V, +/- 10%, X7S, 1206", Cap_Case=1206_180, Manufacturer=TDK, Supplier Part Number 1=445-5207-1-ND, TempCo=X7S, Tolerance_%=10%, Value1="0.005718 ohm", Value2=100V, ValueDisplayed=2.2uF
C17: library part CMP-0006618-1, "CAP, CERM, 0.1 uF, 100 V, +/- 10%, X5R, 0402", Cap_Case=0402, Manufacturer=MuRata, Supplier Part Number 1=490-10458-1-ND, TempCo=X5R, Tolerance_%=10%, Value1=Unknown, Value2=100V, ValueDisplayed=0.1uF
C18: library part CMP-00860000-2, "CAPACITOR, X5R, 0402, 16V, 1UF", Manufacturer=AVX, TempCo=15%, Tolerance_%=10%
C19: library part CMP-0064914-1, "CAP, CERM, 10 pF, 10 V,+/- 2.5%, C0G/NP0, 0402", Cap_Case=0402, Manufacturer=Kemet, Supplier Part Number 1=399-8939-1-ND, TempCo=C0G/NP0, Tolerance_%=2.5%, Value1=Unknown, Value2=10V, ValueDisplayed=10pF
C21 C22: library part CMP-0007108-2, "CAP, CERM, 22 uF, 10 V, +/- 20%, X5R, 0603", Cap_Case=0603, Manufacturer="Samsung Electro-Mechanics", TempCo=X5R, Tolerance_%=20%, Value1=Unknown, Value2=10V, ValueDisplayed=22uF
C24: library part CMP-0007891-2, "CAP, CERM, 1 uF, 100 V, +/- 10%, X7S, 0805", Cap_Case=0805, Manufacturer=TDK, Supplier Part Number 1=445-5205-1-ND, TempCo=X7S, Tolerance_%=10%, Value1="0.008255 ohm", Value2=100V, ValueDisplayed=1uF
C25: library part CMP-0007091-5, "CAP, CERM, 2.2 uF, 10 V, +/- 10%, X5R, AEC-Q200 Grade 3, 0603", Cap_Case=0603, Manufacturer=TDK, Supplier Part Number 1=445-12444-1-ND, TempCo=X5R, Tolerance_%=10%, Value1=Unknown, Value2=10V, ValueDisplayed=2.2uF
C27 C28: library part CMP-0006944-4, "CAP, CERM, 0.47 uF, 16 V, +/- 10%, X7R, 0603", Cap_Case=0603, Manufacturer=Kemet, Supplier Part Number 1=399-4922-1-ND, TempCo=X7R, Tolerance_%=10%, Value1=Unknown, Value2=16V, ValueDisplayed=0.47uF
C29 C48 C61: library part CMP-0093675-1, "4.7uF ±10% 100V Ceramic Capacitor X7S 1210 (3225 Metric)", Manufacturer=Murata, Operating Temperature Range="-55°C to +125°C", TempCo=22%, Temperature Characteristic=X7S, Tolerance_%=10%, ValueDisplayed=4.7uF
C30 C31 C32 C33 C37 C40 C43 C57 C64 C68: library part CMP-0081011-1, "CAP, CERM, 0.1 µF, 100 V,+/- 10%, X7R, AEC-Q200 Grade 1, 0603", Cap_Case=0603, Manufacturer="Taiyo Yuden", Supplier Part Number 1=587-6009-1-ND, TempCo=X7R, Tolerance_%=10%, Value2=100V, ValueDisplayed=0.1µF
C34: library part CMP-0007130-4, "CAP, CERM, 100 pF, 100 V, +/- 5%, C0G/NP0, AEC-Q200 Grade 1, 0603", Cap_Case=0603, Manufacturer=MuRata, Supplier Part Number 1=490-4771-1-ND, TempCo=C0G/NP0, Tolerance_%=5%, Value1=Unknown, Value2=100V, ValueDisplayed=100pF
C35 C36: library part CMP-0006722-4, "CAP, CERM, 33 pF, 100 V, +/- 5%, C0G/NP0, 0603", Cap_Case=0603, Manufacturer=AVX, Supplier Part Number 1=478-1143-1-ND, TempCo=C0G/NP0, Tolerance_%=5%, Value1="0.209 ohm", Value2=100V, ValueDisplayed=33pF
C38 C39: library part CMP-0006753-4, "CAP, CERM, 0.1 uF, 25 V, +/- 10%, X7R, 0603", Cap_Case=0603, Manufacturer=AVX, Supplier Part Number 1=478-3714-1-ND, TempCo=X7R, Tolerance_%=10%, Value1="0.05 ohm", Value2=25V, ValueDisplayed=0.1uF
C41 C54 C60 C63 C69: library part CMP-0861070-1, "CAP, CERM, 1 µF, 100 V,+/- 10%, X7R, AEC-Q200 Grade 1, 0805", Cap_Case=0805, Manufacturer=AVX, TempCo=X7R, Tolerance_%=10%, Value2=100V, ValueDisplayed=1µF
C42 C47: library part CMP-0093626-1, "Cap Ceramic 4.7uF 25V X7R 10% Pad SMD 0805 +125°C Automotive T/R", Manufacturer="TDK Corporation", Operating Temperature Range="-55°C to +125°C", TempCo=15%, Temperature Characteristic=X7R, Tolerance_%=0.1%, ValueDisplayed=4.7uF
C44 C49 C51 C67: library part CMP-0089206-1, "100uF 63V Polymer ALUM Electrolytic Capacitor, CR Series 4000h 10.3x10.3x12.6mm", Digikey Part Number=493-13783-1-ND, Leakage Current=189uA, Manufacturer=Nichicon, Mouser Part Number=647-PCR1J101MCL1GS, Operating Temperature Range="-55°C to +125°C", Tolerance_%=20%, ValueDisplayed=100uF
C53 C59: library part CMP-0096021-1, "10 µF ±10% 100V Ceramic Capacitor X7R 1210 (3225 Metric)", Digikey Part Number=445-C3225X7R2A106K250ACCT-ND, Manufacturer=TDK, Mouser Part Number=810-C3225X7R2A106K25, Operating Temperature Range="-55°C to +125°C", TempCo=15%, Temperature Characteristic=X7R, Tolerance_%=10%, ValueDisplayed=10uF
C56: library part CMP-0007237-3, "Multilayer Ceramic Capacitors MLCC - SMD/SMT CGA 0603 100V 100pF C0G 5% AEC-Q200", Cap_Case=0603, Manufacturer=TDK, Supplier Part Number 1=490-1351-1-ND, TempCo=C0G/NP0, Tolerance_%=5%, Value1=Unknown, Value2=100V, ValueDisplayed=100pF
C58 C62: library part CMP-0012603-3, "CAP, Polymer Hybrid, 56 uF, 63 V, +/- 20%, 30 ohm, 10x10 SMD", Manufacturer=Panasonic, Supplier Part Number 1=P15469CT-ND, Tolerance_%=20%, Value1="30 ohm", Value2=63V, ValueDisplayed=56uF
D1 D2: library part CMP-0006065-2, "Diode, TVS, Bi, 5 V, SOD323, 2-Leads, Body 1.9x1.45mm, No Polarity Mark", Manufacturer=Bourns, Value1=350W
D3: library part CMP-0005905-4, "Diode, Zener, 9.1 V, 300 mW, SOD-523", Manufacturer="Diodes Inc.", Power_W=300mW, Value1=0.3W
D4 D5: library part CMP-0093639-2, "Diode Schottky 1A Surface Mount DO-219AB (SMF)", Digikey Part Number=112-V1FM10-M3/HCT-ND, Forward Current=1A, Manufacturer=Vishay, Max Surge Forward Current=30A, Mouser Part Number=78-V1FM10-M3/H, Operating Temperature Range="-40°C to +175°C", Peak Reverse Current=0.2uA, ValueDisplayed=95pF
J2: library part CMP-0085712-2, "Receptacle, USB 3.1 Type C, R/A, Gold, SMT", Color=Black, Current_A=1.25A, Manufacturer="JAE Electronics", Voltage_V=20V
J3: library part CMP-0075352-1, "Terminal Block, 3.5mm, 3x1, Tin, R/A, TH", Color=Blue, Current_A=10A, Manufacturer="On-Shore Technology", Supplier Part Number 1=ED2636-ND, Voltage_V=125V
J4: library part CMP-0055312-1, "Header, 100mil, 2x1, Tin, TH", Manufacturer=Molex, Supplier Part Number 1=WM8072-ND
J6: library part CMP-0054550-2, "Header, 100mil, 5x2, Tin, TH", Color=Black, Current_A=3A, Manufacturer="Sullins Connector Solutions", Supplier Part Number 1=S2012E-05-ND, Voltage_V=1.8kV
